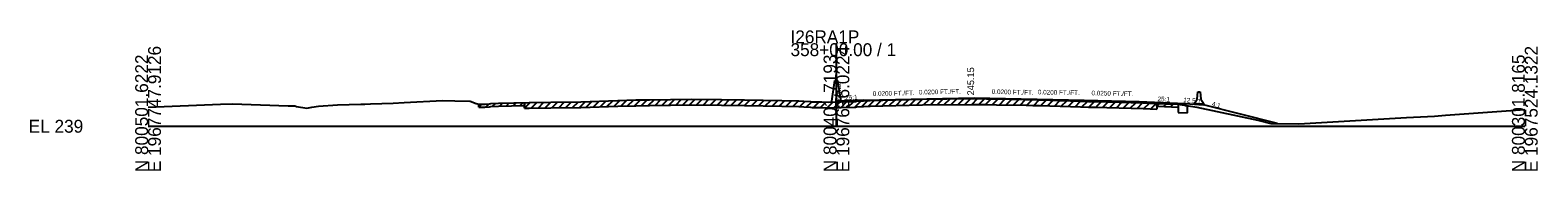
# Model space of a CAD drawing. Extents: x -26 to 304, y -10 to 7527.
# Drawn here: x -25.7 to 302.8, y 3990.3 to 4020.9 of the extents above; entities that cross this region are included whole.
import ezdxf

# ---------------------------------------------------------------- set-up
doc = ezdxf.new("R2010")
doc.units = 0
for name, color, linetype in [('Default', 7, 'Continuous'), ('RD_GPK_XS_Cell', 7, 'Continuous'), ('RD_XS_Base', 7, 'Continuous'), ('RD_XS_Box', 7, 'Continuous'), ('RD_XS_EarthShd', 7, 'Continuous'), ('RD_XS_ExGround', 7, 'Continuous'), ('RD_XS_ExPaveRet', 7, 'Continuous'), ('RD_XS_Misc_Line', 7, 'Continuous'), ('RD_XS_Pave', 7, 'Continuous'), ('RD_XS_PaveShd', 7, 'Continuous'), ('RD_XS_TX_Elev_EX', 7, 'Continuous'), ('RD_XS_TX_Elev_PR', 7, 'Continuous'), ('RD_XS_TX_Misc', 7, 'Continuous'), ('RD_XS_TX_MkPT', 7, 'Continuous'), ('RD_XS_TX_Profile', 7, 'Continuous'), ('RD_XS_TX_Station', 7, 'Continuous')]:
    doc.layers.add(name, color=color, linetype=linetype)

msp = doc.modelspace()

# ---------------------------------------------------------------- linework, layer by layer
at = {"layer": 'Default'}
for p, q in [((228, 4005.06), (228.58, 4005.89)), ((228, 4004.81), (228, 4005.06)), ((228.58, 4005.89), (228.75, 4007.47)), ((228.75, 4007.47), (229.25, 4007.47)), ((229.25, 4007.47), (229.42, 4005.89)), ((229.42, 4005.89), (230, 4005.06)), ((230, 4005.06), (230, 4004.81)), ((230, 4004.81), (228, 4004.81))]:
    msp.add_line(p, q, dxfattribs=at)
at = {"layer": 'RD_GPK_XS_Cell'}
for p, q in [((150, 4000), (150, 4018.06)), ((0, 4000), (150, 4000)), ((150, 4000), (300, 4000))]:
    msp.add_line(p, q, dxfattribs=at)
at = {"layer": 'RD_XS_Base'}
for p, q in [((150, 4005.32), (150, 4005.43)), ((226, 4004.41), (226, 4004.97)), ((224.48, 4002.99), (226.5, 4002.91)), ((226.5, 4004.39), (226, 4004.41)), ((226.5, 4002.91), (226.5, 4004.39))]:
    msp.add_line(p, q, dxfattribs=at)
at = {"layer": 'RD_XS_Box'}
msp.add_line((246.12, 4000.62), (230, 4004.65), dxfattribs=at)
at = {"layer": 'RD_XS_EarthShd'}
for p, q in [((149, 4005.45), (149.67, 4009.93)), ((150, 4009.93), (149.67, 4009.93)), ((150, 4009.93), (150.33, 4009.93)), ((151, 4005.45), (150.33, 4009.93)), ((226, 4004.97), (230, 4004.65))]:
    msp.add_line(p, q, dxfattribs=at)
at = {"layer": 'RD_XS_ExGround'}
msp.add_lwpolyline([(0, 4004.14), (15.82, 4004.78), (18.46, 4004.87), (20.45, 4004.78), (24.52, 4004.69), (30.5, 4004.44), (31.98, 4004.41), (32.31, 4004.3), (34.61, 4003.95), (35.7, 4004.18), (37.17, 4004.34), (41.27, 4004.66), (46.35, 4004.82), (47.2, 4004.84), (48.47, 4004.88), (53.4, 4005.04), (55.84, 4005.16), (64.15, 4005.64), (66.86, 4005.52), (70.19, 4005.43), (71.53, 4004.93), (72.07, 4004.8), (73.38, 4004.81), (74.42, 4004.85), (74.72, 4004.95), (76.34, 4005), (83.08, 4005.19), (87.76, 4005.25), (94.28, 4005.35), (102.4, 4005.6), (106.26, 4005.72), (109.23, 4005.77), (118.4, 4005.92), (124.99, 4005.83), (129.94, 4005.76), (138.11, 4005.6), (141.81, 4005.53), (142.92, 4005.48), (144.32, 4005.42), (144.7, 4005.34), (146.79, 4005.3), (148.37, 4005.27), (150.26, 4005.32), (151.01, 4005.34), (154.15, 4005.39), (154.39, 4005.48), (155.92, 4005.55), (157.32, 4005.62), (162.92, 4005.78), (168.75, 4005.92), (179.61, 4006.01), (180.89, 4006.02), (182.69, 4005.99), (184.87, 4005.94), (191.37, 4005.81), (192.83, 4005.79), (194.24, 4005.74), (201, 4005.53), (203.15, 4005.47), (204.93, 4005.41), (206.28, 4005.38), (216.85, 4005.09), (221.45, 4004.91), (224.48, 4004.79), (228.51, 4004.12), (241.83, 4001.32), (244.64, 4000.63), (250.74, 4000.55), (274.19, 4001.94), (280.33, 4002.22), (282.69, 4002.39), (300, 4003.63)], dxfattribs=at)
at = {"layer": 'RD_XS_ExPaveRet'}
for p, q in [((82, 4003.91), (82, 4005.16)), ((82, 4005.16), (82, 4004.54)), ((219.79, 4004.98), (219.79, 4003.73)), ((219.79, 4004.35), (219.79, 4004.98)), ((72.07, 4004.17), (72.07, 4004.8)), ((72.07, 4004.17), (73.38, 4004.19)), ((73.38, 4004.19), (74.42, 4004.23)), ((74.42, 4004.23), (74.72, 4004.33)), ((74.72, 4004.33), (76.34, 4004.37)), ((76.34, 4004.37), (82, 4004.54)), ((82, 4003.91), (83.08, 4003.94)), ((83.08, 4003.94), (87.76, 4004)), ((87.76, 4004), (94.28, 4004.1)), ((94.28, 4004.1), (102.4, 4004.35)), ((102.4, 4004.35), (106.26, 4004.47)), ((106.26, 4004.47), (109.23, 4004.52)), ((109.23, 4004.52), (118.4, 4004.67)), ((118.4, 4004.67), (124.99, 4004.58)), ((124.99, 4004.58), (129.94, 4004.51)), ((129.94, 4004.51), (138.11, 4004.35)), ((138.11, 4004.35), (141.81, 4004.28)), ((141.81, 4004.28), (142.92, 4004.23)), ((142.92, 4004.23), (144.32, 4004.17)), ((144.32, 4004.17), (144.7, 4004.09)), ((144.7, 4004.09), (146.79, 4004.05)), ((146.79, 4004.05), (148.37, 4004.02)), ((148.37, 4004.02), (150.26, 4004.07)), ((150.26, 4004.07), (151.01, 4004.09)), ((151.01, 4004.09), (154.15, 4004.14)), ((154.15, 4004.14), (154.39, 4004.23)), ((154.39, 4004.23), (155.92, 4004.3)), ((155.92, 4004.3), (157.32, 4004.37)), ((157.32, 4004.37), (162.92, 4004.53)), ((162.92, 4004.53), (168.75, 4004.67)), ((168.75, 4004.67), (179.61, 4004.76)), ((179.61, 4004.76), (180.89, 4004.77)), ((180.89, 4004.77), (182.69, 4004.74)), ((182.69, 4004.74), (184.87, 4004.69)), ((184.87, 4004.69), (191.37, 4004.56)), ((191.37, 4004.56), (192.83, 4004.54)), ((192.83, 4004.54), (194.24, 4004.49)), ((194.24, 4004.49), (201, 4004.28)), ((201, 4004.28), (203.15, 4004.22)), ((203.15, 4004.22), (204.93, 4004.16)), ((204.93, 4004.16), (206.28, 4004.13)), ((206.28, 4004.13), (216.85, 4003.84)), ((216.85, 4003.84), (219.79, 4003.73)), ((219.79, 4004.35), (221.45, 4004.29)), ((221.45, 4004.29), (224.48, 4004.16)), ((224.48, 4004.79), (224.48, 4004.16))]:
    msp.add_line(p, q, dxfattribs=at)
at = {"layer": 'RD_XS_Misc_Line'}
for p, q in [((73.57, 4004.2), (74.22, 4004.84)), ((75.07, 4004.34), (75.71, 4004.98)), ((76.57, 4004.38), (77.21, 4005.02)), ((78.07, 4004.42), (78.71, 4005.07)), ((79.57, 4004.47), (80.21, 4005.11)), ((81.07, 4004.51), (81.71, 4005.15)), ((82, 4003.91), (83.28, 4005.19)), ((83.5, 4003.95), (84.77, 4005.21)), ((85, 4003.97), (86.27, 4005.23)), ((86.5, 4003.99), (87.77, 4005.25)), ((88, 4004.01), (89.27, 4005.28)), ((89.5, 4004.03), (90.77, 4005.3)), ((91, 4004.05), (92.27, 4005.32)), ((92.5, 4004.07), (93.77, 4005.34)), ((94, 4004.09), (95.29, 4005.38)), ((95.5, 4004.14), (96.79, 4005.43)), ((97, 4004.18), (98.29, 4005.47)), ((98.5, 4004.23), (99.79, 4005.52)), ((100, 4004.28), (101.29, 4005.56)), ((101.5, 4004.32), (102.79, 4005.61)), ((103, 4004.37), (104.29, 4005.66)), ((104.5, 4004.41), (105.79, 4005.7)), ((106, 4004.46), (107.28, 4005.73)), ((107.5, 4004.49), (108.77, 4005.76)), ((109, 4004.51), (110.27, 4005.78)), ((110.5, 4004.54), (111.77, 4005.81)), ((112, 4004.56), (113.27, 4005.83)), ((113.5, 4004.59), (114.77, 4005.86)), ((115, 4004.61), (116.27, 4005.88)), ((116.5, 4004.63), (117.77, 4005.91)), ((118, 4004.66), (119.25, 4005.91)), ((119.5, 4004.65), (120.73, 4005.89)), ((121, 4004.63), (122.23, 4005.87)), ((122.5, 4004.61), (123.73, 4005.85)), ((124, 4004.6), (125.23, 4005.83)), ((125.5, 4004.57), (126.73, 4005.81)), ((127, 4004.55), (128.23, 4005.78)), ((128.5, 4004.53), (129.73, 4005.76)), ((130, 4004.51), (131.23, 4005.73)), ((131.5, 4004.48), (132.73, 4005.7)), ((133, 4004.45), (134.23, 4005.67)), ((134.5, 4004.42), (135.73, 4005.64)), ((136, 4004.39), (137.23, 4005.61)), ((137.5, 4004.36), (138.73, 4005.59)), ((139, 4004.33), (140.23, 4005.56)), ((140.5, 4004.31), (141.73, 4005.53)), ((142, 4004.27), (143.19, 4005.47)), ((143.5, 4004.2), (144.65, 4005.35)), ((145, 4004.08), (146.23, 4005.31)), ((146.5, 4004.05), (147.73, 4005.28)), ((148, 4004.02), (149.27, 4005.29)), ((149.5, 4004.05), (150.79, 4005.34)), ((151, 4004.09), (152.27, 4005.36)), ((152.5, 4004.12), (153.77, 4005.39)), ((154, 4004.14), (155.39, 4005.53)), ((155.5, 4004.28), (156.81, 4005.6)), ((157, 4004.35), (158.29, 4005.65)), ((158.5, 4004.4), (159.79, 4005.69)), ((160, 4004.44), (161.29, 4005.73)), ((161.5, 4004.49), (162.79, 4005.77)), ((163, 4004.53), (164.28, 4005.81)), ((164.5, 4004.56), (165.78, 4005.85)), ((166, 4004.6), (167.28, 4005.88)), ((167.5, 4004.64), (168.78, 4005.92)), ((169, 4004.67), (170.26, 4005.93)), ((170.5, 4004.68), (171.76, 4005.95)), ((172, 4004.7), (173.26, 4005.96)), ((173.5, 4004.71), (174.76, 4005.97)), ((175, 4004.72), (176.26, 4005.98)), ((176.5, 4004.74), (177.76, 4006)), ((178, 4004.75), (179.26, 4006.01)), ((179.5, 4004.76), (180.76, 4006.02)), ((181, 4004.77), (182.23, 4006)), ((182.5, 4004.74), (183.73, 4005.97)), ((184, 4004.71), (185.22, 4005.94)), ((185.5, 4004.68), (186.73, 4005.91)), ((187, 4004.65), (188.23, 4005.88)), ((188.5, 4004.62), (189.73, 4005.85)), ((190, 4004.59), (191.23, 4005.82)), ((191.5, 4004.56), (192.73, 4005.79)), ((193, 4004.53), (194.21, 4005.74)), ((194.5, 4004.48), (195.71, 4005.7)), ((196, 4004.44), (197.21, 4005.65)), ((197.5, 4004.39), (198.71, 4005.6)), ((199, 4004.35), (200.21, 4005.56)), ((200.5, 4004.3), (201.71, 4005.51)), ((202, 4004.25), (203.21, 4005.47)), ((203.5, 4004.21), (204.71, 4005.42)), ((205, 4004.16), (206.22, 4005.38)), ((206.5, 4004.12), (207.72, 4005.34)), ((208, 4004.08), (209.22, 4005.3)), ((209.5, 4004.04), (210.72, 4005.26)), ((211, 4004), (212.22, 4005.22)), ((212.5, 4003.96), (213.72, 4005.18)), ((214, 4003.92), (215.22, 4005.13)), ((215.5, 4003.88), (216.72, 4005.09)), ((217, 4003.83), (218.2, 4005.04)), ((218.5, 4003.78), (219.7, 4004.98)), ((219.79, 4004.35), (220.39, 4004.95)), ((221.29, 4004.29), (221.89, 4004.89)), ((222.79, 4004.23), (223.39, 4004.83)), ((72.07, 4004.17), (72.7, 4004.81))]:
    msp.add_line(p, q, dxfattribs=at)
at = {"layer": 'RD_XS_Pave'}
for p, q in [((156, 4005.67), (180, 4006.15)), ((180, 4006.15), (204, 4005.67)), ((204, 4005.67), (216, 4005.37))]:
    msp.add_line(p, q, dxfattribs=at)
at = {"layer": 'RD_XS_PaveShd'}
for p, q in [((156, 4005.67), (150, 4005.43)), ((216, 4005.37), (226, 4004.97))]:
    msp.add_line(p, q, dxfattribs=at)
at = {"layer": 'RD_XS_TX_Elev_PR'}
for p, q in [((150, 4005.32), (150.26, 4005.32)), ((150.26, 4005.32), (151.01, 4005.34)), ((151.01, 4005.34), (154.15, 4005.39)), ((154.15, 4005.39), (154.39, 4005.48)), ((154.39, 4005.48), (155.92, 4005.55)), ((155.92, 4005.55), (157.32, 4005.62)), ((157.32, 4005.62), (162.92, 4005.78)), ((162.92, 4005.78), (168.75, 4005.92)), ((168.75, 4005.92), (179.61, 4006.01)), ((179.61, 4006.01), (180.89, 4006.02)), ((180.89, 4006.02), (182.69, 4005.99)), ((182.69, 4005.99), (184.87, 4005.94)), ((184.87, 4005.94), (191.37, 4005.81)), ((191.37, 4005.81), (192.83, 4005.79)), ((192.83, 4005.79), (194.24, 4005.74)), ((194.24, 4005.74), (201, 4005.53)), ((201, 4005.53), (203.15, 4005.47)), ((203.15, 4005.47), (204.93, 4005.41)), ((204.93, 4005.41), (206.28, 4005.38)), ((206.28, 4005.38), (216.85, 4005.09)), ((216.85, 4005.09), (219.79, 4004.98)), ((219.79, 4004.98), (222.97, 4004.85)), ((222.97, 4004.85), (224.48, 4004.79)), ((224.48, 4004.79), (224.48, 4002.99))]:
    msp.add_line(p, q, dxfattribs=at)

# ---------------------------------------------------------------- texts
at = {"layer": 'RD_GPK_XS_Cell'}
for s, p in [('358+00.00 / 1', (140, 4015.26)), ('I26RA1P', (140, 4018.06)), ('EL 239', (-26, 3998.6))]:
    msp.add_text(s, height=2.8, dxfattribs=at).set_placement(p)
for s, p in [('N 800501.6222', (0, 3990)), ('E 1967747.9126', (2.8, 3990)), ('N 800401.7193', (150, 3990)), ('E 1967636.0224', (152.8, 3990)), ('N 800301.8165', (300, 3990)), ('E 1967524.1322', (302.8, 3990))]:
    msp.add_text(s, height=2.8, rotation=90, dxfattribs=at).set_placement(p)
at = {"layer": 'RD_XS_TX_Elev_EX'}
msp.add_text('244.32', height=1, rotation=90, dxfattribs=at).set_placement((151, 4005.32))
at = {"layer": 'RD_XS_TX_Misc'}
msp.add_text('12.5:1', height=1, rotation=355.4261, dxfattribs=at).set_placement((225.54, 4005.25))
at = {"layer": 'RD_XS_TX_MkPT'}
for rotation, p in [(2.2906, (151.94, 4005.75)), (357.7094, (219.96, 4005.46))]:
    msp.add_text('25:1', height=1, rotation=rotation, dxfattribs=at).set_placement(p)
at = {"layer": 'RD_XS_TX_Profile'}
for s, rotation, p in [('0.0200 FT./FT.', 1.1458, (157.92, 4006.59)), ('0.0200 FT./FT.', 1.1458, (167.98, 4006.91)), ('0.0200 FT./FT.', 358.5679, (183.83, 4007.05)), ('0.0200 FT./FT.', 358.8542, (193.89, 4006.95)), ('0.0250 FT./FT.', 358.8542, (205.57, 4006.75)), ('4:1', 345.9638, (231.72, 4004.43))]:
    msp.add_text(s, height=1, rotation=rotation, dxfattribs=at).set_placement(p)
at = {"layer": 'RD_XS_TX_Station'}
msp.add_text(' 245.15', height=1.5, rotation=90, dxfattribs=at).set_placement((180, 4006.15))

doc.saveas('drawing.dxf')
